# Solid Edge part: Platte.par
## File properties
Sűrűség: 0,000 kg/m^3
Pontosság: 0,990
Author: bmolnar
Last saved by: bmolnar
Revision: 77
Username: bmolnar
Dokumentum tartalom típus: 0
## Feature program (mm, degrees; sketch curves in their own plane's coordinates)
base feature "unnamed BaseFeature 1"
thread "unnamed Thread 1"
thread "unnamed Thread 2"
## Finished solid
Body 1: solid body, 177 faces, 438 edges, 260 vertices, 2 internal voids.
  Faces by surface: plane 82, cylinder 72, cone 20, torus 3
  Edges by curve: line 256, circle 164, spline 18
Bounding box of the edges (mm; curved faces can reach further): 113.500 x 113.500 x 14.000, from (-56.75, -56.75, -121.45) to (56.75, 56.75, -107.45).
Cylindrical faces by radius (mm): R0.15 x24, R0.25 x24, R1 x4, R4.188 x2, R4.55 x2, R5 x2, R6.5 x2, R6.75 x2, R8 x2, R9 x1, R12.25 x4, R15 x1, R35 x2
Conical faces (half-angle, radius in mm at the cone's reference point): 45 deg R4.5 x2, 45 deg R4.538 x4, 45 deg R5.15 x4, 45 deg R6.9 x2, 45 deg R8.15 x4, 45 deg R15.15 x1, 60 deg R1.4434 x2, 60 deg R2.3094 x1
Toroidal faces (ring radius, tube radius in mm): R5.7 r0.8 x2, R7.8 r1.2 x1
Planar faces by outward normal: +x 13, +y 17, +z 3, -x 13, -y 17, -z 7, oblique 12
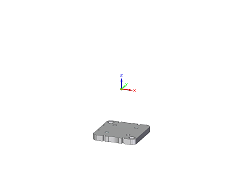
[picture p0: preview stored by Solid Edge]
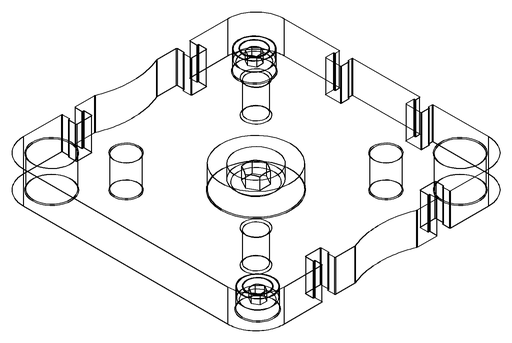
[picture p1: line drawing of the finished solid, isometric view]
